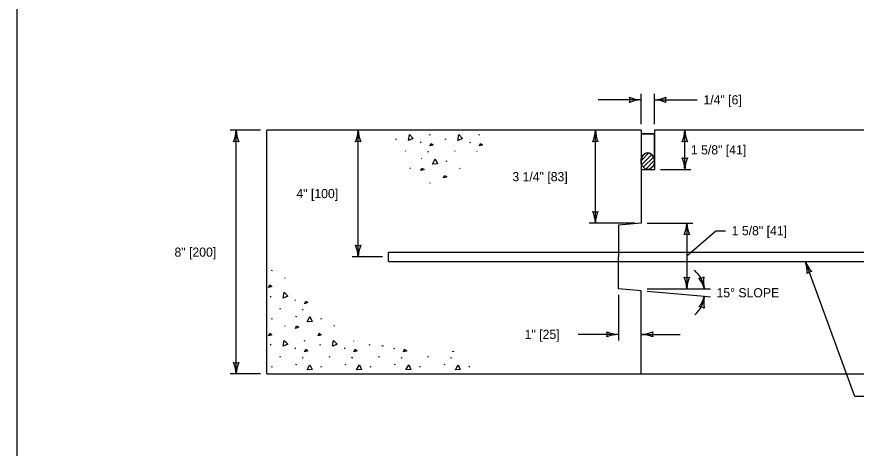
# Model space of a CAD drawing. Extents: x 49991.4 to 50021, y 49987.6 to 50011.4.
# Drawn here: x 50000.34 to 50005.84, y 50005.57 to 50008.4 of the extents above; entities that cross this region are included whole.
import ezdxf

# ---------------------------------------------------------------- set-up
doc = ezdxf.new("R2010")
doc.units = 0
for name, color, linetype in [('Level 1', 7, 'Continuous'), ('Level 2', 7, 'Continuous'), ('Level 3', 7, 'Continuous')]:
    doc.layers.add(name, color=color, linetype=linetype)

msp = doc.modelspace()

# ---------------------------------------------------------------- linework, layer by layer
at = {"layer": 'Level 1'}
for p, q in [((50001.9751, 50006.058), (50001.9751, 50007.658)), ((50003.0448, 50007.6261), (50003.0475, 50007.6322)), ((50003.3689, 50007.6261), (50003.3716, 50007.6322)), ((50004.4317, 50007.658), (50004.4317, 50007.4011)), ((50004.4317, 50007.635), (50004.5185, 50007.635)), ((50004.5185, 50007.658), (50004.5185, 50007.4011)), ((50002.8235, 50007.5983), (50002.8262, 50007.6044)), ((50002.9844, 50007.5813), (50002.9851, 50007.5753)), ((50003.1477, 50007.5983), (50003.1504, 50007.6044)), ((50003.3085, 50007.5813), (50003.3092, 50007.5753)), ((50002.8851, 50007.5198), (50002.8878, 50007.5259)), ((50003.2092, 50007.5198), (50003.2119, 50007.5259)), ((50002.9907, 50007.4697), (50002.9934, 50007.4758)), ((50003.0306, 50007.5198), (50003.0333, 50007.5158)), ((50003.0333, 50007.5183), (50003.036, 50007.5142)), ((50003.3547, 50007.5198), (50003.3554, 50007.5188)), ((50004.4318, 50007.4575), (50004.4833, 50007.5091)), ((50004.4357, 50007.4331), (50004.5014, 50007.4989)), ((50004.446, 50007.4152), (50004.513, 50007.4821)), ((50003.1544, 50007.4541), (50003.1571, 50007.4602)), ((50004.4626, 50007.4035), (50004.5183, 50007.4592)), ((50004.4941, 50007.4067), (50004.5088, 50007.4214)), ((50002.9149, 50007.4108), (50002.9176, 50007.4068)), ((50003.239, 50007.4108), (50003.2417, 50007.4068)), ((50004.4317, 50007.4011), (50004.5185, 50007.4011)), ((50003.0448, 50007.31), (50003.0475, 50007.3161)), ((50004.2823, 50007.0356), (50004.2823, 50006.8267)), ((50002.7751, 50006.7955), (50002.7751, 50006.858)), ((50004.2823, 50006.6178), (50004.2823, 50006.8267)), ((50002.0078, 50006.7346), (50002.0105, 50006.7407)), ((50002.0924, 50006.6913), (50002.0951, 50006.6873)), ((50002.001, 50006.5627), (50002.0037, 50006.5688)), ((50002.1619, 50006.5457), (50002.1626, 50006.5397)), ((50002.0626, 50006.4843), (50002.0653, 50006.4903)), ((50002.2081, 50006.4843), (50002.2108, 50006.4802)), ((50002.2108, 50006.4827), (50002.2135, 50006.4787)), ((50002.0078, 50006.4185), (50002.0105, 50006.4246)), ((50002.1682, 50006.4341), (50002.1709, 50006.4402)), ((50002.3319, 50006.4185), (50002.3346, 50006.4246)), ((50002.0924, 50006.3752), (50002.0951, 50006.3712)), ((50002.4165, 50006.3752), (50002.4192, 50006.3712)), ((50002.2223, 50006.2744), (50002.225, 50006.2805)), ((50002.5464, 50006.2744), (50002.5469, 50006.2754)), ((50002.001, 50006.2467), (50002.0037, 50006.2527)), ((50002.1619, 50006.2297), (50002.1626, 50006.2236)), ((50002.3252, 50006.2467), (50002.3279, 50006.2527)), ((50002.486, 50006.2297), (50002.4867, 50006.2236)), ((50002.6493, 50006.2467), (50002.652, 50006.2527)), ((50002.8102, 50006.2297), (50002.8109, 50006.2236)), ((50002.0626, 50006.1682), (50002.0653, 50006.1743)), ((50002.2081, 50006.1682), (50002.2108, 50006.1641)), ((50002.2108, 50006.1666), (50002.2135, 50006.1626)), ((50002.3867, 50006.1682), (50002.3894, 50006.1743)), ((50002.5322, 50006.1682), (50002.5349, 50006.1641)), ((50002.5349, 50006.1666), (50002.5376, 50006.1626)), ((50002.7109, 50006.1682), (50002.7136, 50006.1743)), ((50002.8564, 50006.1682), (50002.8591, 50006.1641)), ((50002.8591, 50006.1666), (50002.8618, 50006.1626)), ((50003.035, 50006.1682), (50003.0377, 50006.1743)), ((50003.1805, 50006.1682), (50003.1832, 50006.1641)), ((50003.1832, 50006.1666), (50003.1859, 50006.1626)), ((50002.0078, 50006.1024), (50002.0105, 50006.1085)), ((50002.1682, 50006.118), (50002.1709, 50006.1241)), ((50002.3319, 50006.1024), (50002.3346, 50006.1085)), ((50002.4923, 50006.118), (50002.495, 50006.1241)), ((50002.6561, 50006.1024), (50002.6588, 50006.1085)), ((50002.8164, 50006.118), (50002.8191, 50006.1241)), ((50002.9802, 50006.1024), (50002.9829, 50006.1085)), ((50003.1406, 50006.118), (50003.1433, 50006.1241)), ((50003.3043, 50006.1024), (50003.3071, 50006.1085)), ((50002.0924, 50006.0591), (50002.0932, 50006.058)), ((50002.4165, 50006.0591), (50002.4173, 50006.058)), ((50002.7407, 50006.0591), (50002.7414, 50006.058)), ((50003.0648, 50006.0591), (50003.0656, 50006.058)), ((50003.3889, 50006.0591), (50003.3897, 50006.058))]:
    msp.add_line(p, q, dxfattribs=at)
msp.add_lwpolyline([(50008.6146, 50011.2628), (50000.3356, 50011.2628), (50000.3356, 50000.0624), (50008.6146, 50000.0624)], close=True, dxfattribs=at)
for points in [[(50001.9751, 50006.058), (50006.9751, 50006.058), (50006.9751, 50007.658), (50004.5185, 50007.658)], [(50004.4317, 50007.658), (50001.9751, 50007.658)], [(50004.5184, 50007.4592), (50004.5185, 50007.4592), (50004.5185, 50007.635), (50004.4317, 50007.635), (50004.4317, 50007.4575), (50004.4317, 50007.4575)], [(50002.9058, 50007.5913), (50002.9112, 50007.63), (50002.9354, 50007.605), (50002.9065, 50007.5916)], [(50003.23, 50007.5913), (50003.2353, 50007.63), (50003.2596, 50007.605), (50003.2306, 50007.5916)], [(50003.0462, 50007.555), (50003.0543, 50007.5719), (50003.0678, 50007.5618), (50003.0462, 50007.555)], [(50003.3703, 50007.555), (50003.3784, 50007.5719), (50003.3919, 50007.5618), (50003.3703, 50007.555)], [(50003.0631, 50007.4359), (50003.0813, 50007.4704), (50003.0955, 50007.4386), (50003.0637, 50007.4359)], [(50002.9859, 50007.3932), (50002.994, 50007.4101), (50003.0076, 50007.4), (50002.9859, 50007.3932)], [(50003.1343, 50007.3449), (50003.1424, 50007.3618), (50003.1559, 50007.3516), (50003.1343, 50007.3449)], [(50004.4317, 50007.4011), (50004.4317, 50007.0487), (50004.2823, 50007.0356)], [(50002.7751, 50006.858), (50006.1751, 50006.858), (50006.1751, 50006.7955)], [(50002.7751, 50006.7955), (50006.1751, 50006.7955)], [(50001.9876, 50006.6253), (50001.9957, 50006.6423), (50002.0093, 50006.6321), (50001.9876, 50006.6253)], [(50002.0834, 50006.5557), (50002.0887, 50006.5944), (50002.1129, 50006.5694), (50002.084, 50006.556)], [(50004.4317, 50006.058), (50004.4317, 50006.6048), (50004.2823, 50006.6178)], [(50002.2237, 50006.5194), (50002.2318, 50006.5364), (50002.2453, 50006.5262), (50002.2237, 50006.5194)], [(50002.2406, 50006.4003), (50002.2589, 50006.4348), (50002.2731, 50006.403), (50002.2413, 50006.4003)], [(50002.1634, 50006.3576), (50002.1715, 50006.3745), (50002.1851, 50006.3644), (50002.1634, 50006.3576)], [(50001.9876, 50006.3093), (50001.9957, 50006.3262), (50002.0093, 50006.316), (50001.9876, 50006.3093)], [(50002.3118, 50006.3093), (50002.3199, 50006.3262), (50002.3334, 50006.316), (50002.3118, 50006.3093)], [(50002.0834, 50006.2397), (50002.0887, 50006.2783), (50002.1129, 50006.2533), (50002.084, 50006.2399)], [(50002.4075, 50006.2397), (50002.4129, 50006.2783), (50002.4371, 50006.2533), (50002.4081, 50006.2399)], [(50002.2237, 50006.2034), (50002.2318, 50006.2203), (50002.2453, 50006.2101), (50002.2237, 50006.2034)], [(50002.5478, 50006.2034), (50002.5559, 50006.2203), (50002.5695, 50006.2101), (50002.5478, 50006.2034)], [(50002.7316, 50006.2397), (50002.7322, 50006.2438)], [(50002.7384, 50006.2428), (50002.7323, 50006.2399)], [(50002.8719, 50006.2034), (50002.8801, 50006.2203), (50002.8936, 50006.2101), (50002.8719, 50006.2034)], [(50003.1961, 50006.2034), (50003.1979, 50006.2071)], [(50003.2038, 50006.2058), (50003.1961, 50006.2034)], [(50002.2406, 50006.0842), (50002.2589, 50006.1187), (50002.2731, 50006.0869), (50002.2413, 50006.0842)], [(50002.5647, 50006.0842), (50002.583, 50006.1187), (50002.5972, 50006.0869), (50002.5654, 50006.0842)], [(50002.8889, 50006.0842), (50002.9071, 50006.1187), (50002.9213, 50006.0869), (50002.8895, 50006.0842)], [(50003.213, 50006.0842), (50003.2313, 50006.1187), (50003.2455, 50006.0869), (50003.2137, 50006.0842)], [(50002.1713, 50006.058), (50002.1715, 50006.0585), (50002.1722, 50006.058)], [(50002.4955, 50006.058), (50002.4957, 50006.0585), (50002.4963, 50006.058)], [(50002.8196, 50006.058), (50002.8198, 50006.0585), (50002.8205, 50006.058)], [(50003.1437, 50006.058), (50003.144, 50006.0585), (50003.1446, 50006.058)]]:
    msp.add_lwpolyline(points, dxfattribs=at)
msp.add_ellipse((50004.4751, 50007.4556), major_axis=(0, -0.0545), ratio=0.796445, dxfattribs=at)
for start_param, end_param in [(3.141593, 4.677812), (1.636616, 3.141593)]:
    msp.add_ellipse((50004.4751, 50007.4556), major_axis=(0, -0.0545), ratio=0.796445, start_param=start_param, end_param=end_param, dxfattribs=at)
at = {"layer": 'Level 3'}
for p, q in [((50004.4317, 50007.858), (50004.1499, 50007.858)), ((50004.4317, 50007.698), (50004.4317, 50007.898)), ((50004.5185, 50007.698), (50004.5185, 50007.898)), ((50004.5185, 50007.858), (50004.8003, 50007.858)), ((50001.9351, 50007.658), (50001.7351, 50007.658)), ((50001.7751, 50006.058), (50001.7751, 50007.658)), ((50002.5751, 50006.8267), (50002.5751, 50007.658)), ((50004.1317, 50007.0487), (50004.1317, 50007.658)), ((50004.7185, 50007.4011), (50004.7185, 50007.658)), ((50004.5585, 50007.4011), (50004.7585, 50007.4011)), ((50004.3917, 50007.0487), (50004.0917, 50007.0487)), ((50004.4717, 50007.0487), (50004.7717, 50007.0487)), ((50004.7317, 50007.0487), (50004.7317, 50006.6178)), ((50004.7317, 50006.8333), (50004.9209, 50006.9985)), ((50004.9209, 50006.9985), (50004.9857, 50006.9985)), ((50002.7351, 50006.8267), (50002.5351, 50006.8267)), ((50004.4715, 50006.6178), (50004.8464, 50006.6178)), ((50004.4715, 50006.6013), (50004.8464, 50006.5685)), ((50004.8464, 50006.6178), (50004.8864, 50006.6178)), ((50004.2823, 50006.5778), (50004.2823, 50006.2778)), ((50004.8464, 50006.5685), (50004.8862, 50006.565)), ((50004.2823, 50006.3178), (50004.0187, 50006.3178)), ((50004.4317, 50006.3178), (50004.6877, 50006.3178)), ((50001.9351, 50006.058), (50001.7351, 50006.058))]:
    msp.add_line(p, q, dxfattribs=at)
msp.add_lwpolyline([(50006.0475, 50005.9095), (50005.8339, 50005.9095), (50005.5097, 50006.7955)], dxfattribs=at)
for centre, radius, start, end in [((50004.4408, 50008.0801), 0.2223, 247.456, 267.6395), ((50004.3035, 50007.858), 0.0548, 342.1388, 17.8612), ((50004.4408, 50008.0801), 0.2223, 247.456, 267.6395), ((50004.3035, 50007.858), 0.0548, 342.1388, 17.8612), ((50004.4432, 50007.6253), 0.233, 92.8273, 112.0772), ((50004.4432, 50007.6253), 0.233, 92.8273, 112.0772), ((50004.507, 50008.0907), 0.233, 272.8273, 292.0772), ((50004.507, 50008.0907), 0.233, 272.8273, 292.0772), ((50004.5094, 50007.6358), 0.2223, 67.456, 87.6395), ((50004.5094, 50007.6358), 0.2223, 67.456, 87.6395), ((50004.6467, 50007.858), 0.0548, 162.1388, 197.8612), ((50004.6467, 50007.858), 0.0548, 162.1388, 197.8612), ((50001.553, 50007.6671), 0.2223, 337.456, 357.6395), ((50001.553, 50007.6671), 0.2223, 337.456, 357.6395), ((50002.0078, 50007.6695), 0.233, 182.8273, 202.0772), ((50002.0078, 50007.6695), 0.233, 182.8273, 202.0772), ((50002.353, 50007.6671), 0.2223, 337.456, 357.6395), ((50002.353, 50007.6671), 0.2223, 337.456, 357.6395), ((50002.8078, 50007.6695), 0.233, 182.8273, 202.0772), ((50002.8078, 50007.6695), 0.233, 182.8273, 202.0772), ((50003.9096, 50007.6671), 0.2223, 337.456, 357.6395), ((50004.3644, 50007.6695), 0.233, 182.8273, 202.0772), ((50004.4964, 50007.6671), 0.2223, 337.456, 357.6395), ((50004.4964, 50007.6671), 0.2223, 337.456, 357.6395), ((50004.9512, 50007.6695), 0.233, 182.8273, 202.0772), ((50004.9512, 50007.6695), 0.233, 182.8273, 202.0772), ((50001.7751, 50007.5298), 0.0548, 72.1388, 107.8612), ((50001.7751, 50007.5298), 0.0548, 72.1388, 107.8612), ((50002.5751, 50007.5298), 0.0548, 72.1388, 107.8612), ((50002.5751, 50007.5298), 0.0548, 72.1388, 107.8612), ((50004.1317, 50007.5298), 0.0548, 72.1388, 107.8612), ((50004.7185, 50007.5298), 0.0548, 72.1388, 107.8612), ((50004.7185, 50007.5298), 0.0548, 72.1388, 107.8612), ((50004.7185, 50007.5293), 0.0548, 252.1388, 287.8612), ((50004.4858, 50007.3896), 0.233, 2.8273, 22.0772), ((50004.7185, 50007.5293), 0.0548, 252.1388, 287.8612), ((50004.4858, 50007.3896), 0.233, 2.8273, 22.0772), ((50004.9406, 50007.392), 0.2223, 157.456, 177.6395), ((50004.9406, 50007.392), 0.2223, 157.456, 177.6395), ((50004.1317, 50007.1769), 0.0548, 252.1388, 287.8612), ((50003.899, 50007.0372), 0.233, 2.8273, 22.0772), ((50004.1317, 50007.1769), 0.0548, 252.1388, 287.8612), ((50003.899, 50007.0372), 0.233, 2.8273, 22.0772), ((50004.3538, 50007.0395), 0.2223, 157.456, 177.6395), ((50004.3538, 50007.0395), 0.2223, 157.456, 177.6395), ((50004.5096, 50007.0579), 0.2223, 337.456, 357.6395), ((50004.5096, 50007.0579), 0.2223, 337.456, 357.6395), ((50004.9644, 50007.0602), 0.233, 182.8273, 202.0772), ((50004.9644, 50007.0602), 0.233, 182.8273, 202.0772), ((50004.7317, 50006.9205), 0.0548, 72.1388, 107.8612), ((50004.7317, 50006.9205), 0.0548, 72.1388, 107.8612), ((50002.5751, 50006.9549), 0.0548, 252.1388, 287.8612), ((50002.3424, 50006.8152), 0.233, 2.8273, 22.0772), ((50002.5751, 50006.9549), 0.0548, 252.1388, 287.8612), ((50002.3424, 50006.8152), 0.233, 2.8273, 22.0772), ((50002.7972, 50006.8176), 0.2223, 157.456, 177.6395), ((50002.7972, 50006.8176), 0.2223, 157.456, 177.6395), ((50005.2979, 50006.7277), 0.2223, 357.558, 17.7415), ((50005.7242, 50006.8863), 0.233, 202.9293, 222.1791), ((50004.66, 50006.5951), 0.1878, 6.9608, 49.9742), ((50004.8142, 50006.7419), 0.0548, 266.6807, 302.403), ((50005.0637, 50006.6647), 0.2223, 171.9978, 192.1814), ((50005.5537, 50006.6751), 0.0548, 92.2408, 127.9631), ((50004.7317, 50006.746), 0.0548, 252.1388, 287.8612), ((50004.499, 50006.6063), 0.233, 2.8273, 22.0772), ((50004.7317, 50006.746), 0.0548, 252.1388, 287.8612), ((50004.499, 50006.6063), 0.233, 2.8273, 22.0772), ((50004.9538, 50006.6087), 0.2223, 157.456, 177.6395), ((50004.9538, 50006.6087), 0.2223, 157.456, 177.6395), ((50004.624, 50006.5483), 0.233, 17.3691, 36.619), ((50004.6591, 50006.5865), 0.1882, 311.8732, 354.5032), ((50004.6326, 50006.6296), 0.2223, 323.8618, 344.0453), ((50005.0753, 50006.5249), 0.233, 169.2331, 188.4829), ((50004.8163, 50006.4439), 0.0548, 58.5446, 94.2669), ((50004.2914, 50006.54), 0.2223, 247.456, 267.6395), ((50004.154, 50006.3178), 0.0548, 342.1388, 17.8612), ((50004.2914, 50006.54), 0.2223, 247.456, 267.6395), ((50004.154, 50006.3178), 0.0548, 342.1388, 17.8612), ((50004.2938, 50006.0851), 0.233, 92.8273, 112.0772), ((50004.2938, 50006.0851), 0.233, 92.8273, 112.0772), ((50004.4202, 50006.5505), 0.233, 272.8273, 292.0772), ((50004.4202, 50006.5505), 0.233, 272.8273, 292.0772), ((50004.4225, 50006.0957), 0.2223, 67.456, 87.6395), ((50004.4225, 50006.0957), 0.2223, 67.456, 87.6395), ((50004.5599, 50006.3178), 0.0548, 162.1388, 197.8612), ((50004.5599, 50006.3178), 0.0548, 162.1388, 197.8612), ((50001.7751, 50006.1862), 0.0548, 252.1388, 287.8612), ((50001.5424, 50006.0465), 0.233, 2.8273, 22.0772), ((50001.7751, 50006.1862), 0.0548, 252.1388, 287.8612), ((50001.5424, 50006.0465), 0.233, 2.8273, 22.0772), ((50001.9972, 50006.0488), 0.2223, 157.456, 177.6395), ((50001.9972, 50006.0488), 0.2223, 157.456, 177.6395)]:
    msp.add_arc(centre, radius, start, end, dxfattribs=at)

# ---------------------------------------------------------------- texts
at = {"layer": 'Level 2'}
for s, p in [('1/4" [6]', (50004.8403, 50007.828)), ('1 5/8" [41]', (50004.7582, 50007.4996)), ('3 1/4" [83]', (50003.5871, 50007.3233)), ('4" [100]', (50002.1701, 50007.2124)), ('1 5/8" [41]', (50005.0257, 50006.9685)), ('8" [200]', (50001.3701, 50006.828)), ('15° SLOPE', (50004.9263, 50006.5614)), ('1" [25]', (50003.6676, 50006.2878))]:
    msp.add_text(s, height=0.06, dxfattribs=at).set_placement(p)

doc.saveas('drawing.dxf')
